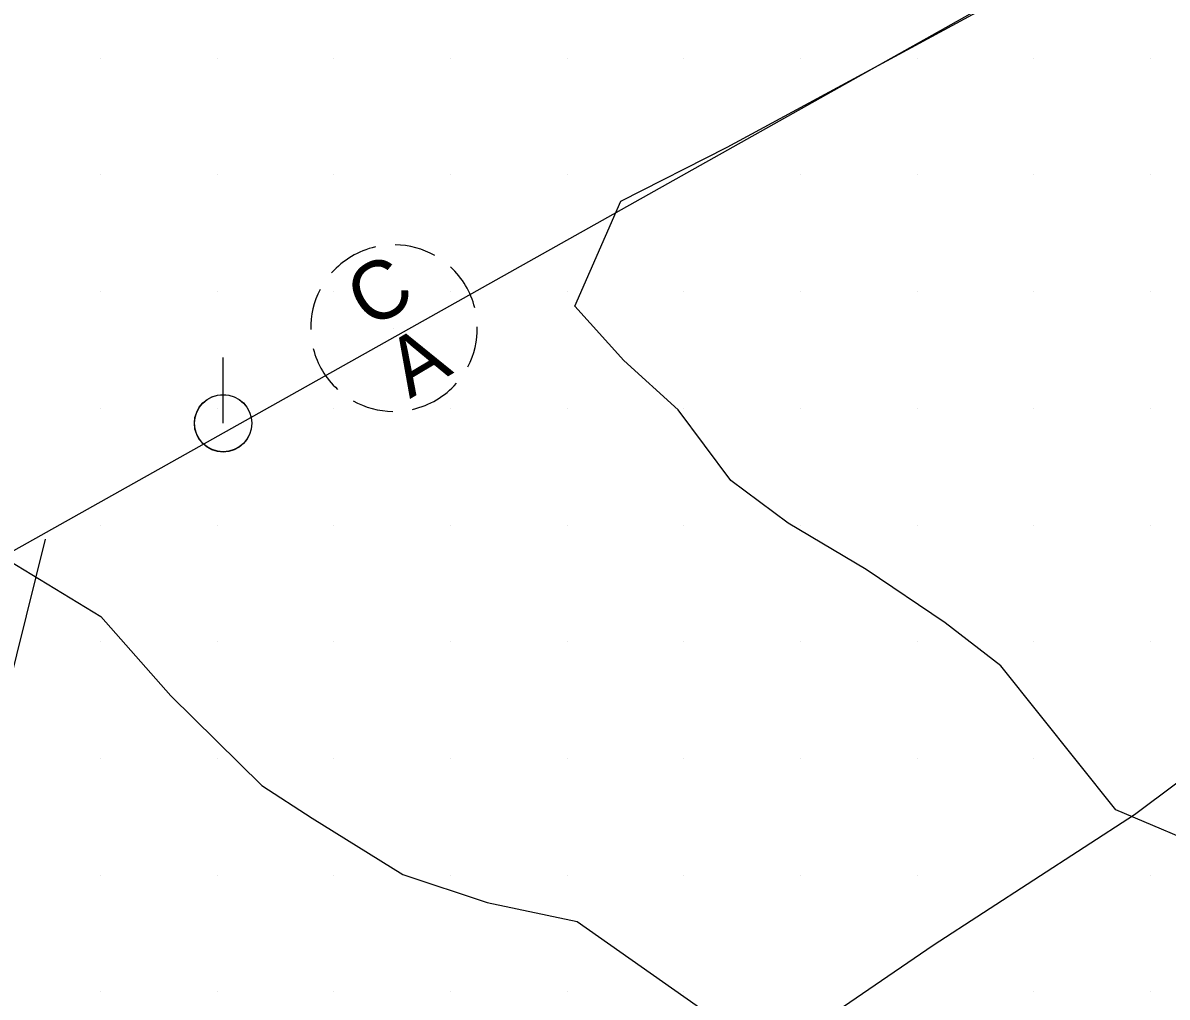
# Model space of a CAD drawing. Extents: x 1548934 to 1561348, y 809680 to 824075.
# Drawn here: x 1551833.4 to 1551931.4, y 810969.6 to 811053 of the extents above; entities that cross this region are included whole.
import ezdxf

# ---------------------------------------------------------------- set-up
doc = ezdxf.new("R2010")
doc.units = 0
for name, color, linetype in [('Exist DTM QL2 LIDAR Elevation Point', 7, 'Continuous'), ('Exist Other Culture Fence Line Leader', 7, 'Continuous'), ('Exist Right of Way Control of Access CA Symbol CELL', 7, 'Continuous'), ('Exist Utilities Other Pole CELL', 7, 'Continuous'), ('Exist Utilities Power Pole CELL', 7, 'Continuous'), ('Exist Vegetation Woods Line', 7, 'Continuous'), ('P_RDY_Dimension_Text', 7, 'Continuous'), ('PH Exist DTM Breakline', 7, 'Continuous')]:
    doc.layers.add(name, color=color, linetype=linetype)

msp = doc.modelspace()

# ---------------------------------------------------------------- linework, layer by layer
at = {"layer": 'Exist DTM QL2 LIDAR Elevation Point'}
for p, q in [((1551840.006, 811050.015), (1551840.006, 811050.015)), ((1551850.007, 811050.015), (1551850.007, 811050.015)), ((1551860.008, 811050.015), (1551860.008, 811050.015)), ((1551870.008, 811050.015), (1551870.008, 811050.015)), ((1551880.009, 811050.015), (1551880.009, 811050.015)), ((1551890.01, 811050.015), (1551890.01, 811050.015)), ((1551900.011, 811050.015), (1551900.011, 811050.015)), ((1551910.012, 811050.015), (1551910.012, 811050.015)), ((1551920.012, 811050.015), (1551920.012, 811050.015)), ((1551930.013, 811050.015), (1551930.013, 811050.015)), ((1551840.006, 811040.014), (1551840.006, 811040.014)), ((1551850.007, 811040.014), (1551850.007, 811040.014)), ((1551860.008, 811040.014), (1551860.008, 811040.014)), ((1551870.008, 811040.014), (1551870.008, 811040.014)), ((1551880.009, 811040.014), (1551880.009, 811040.014)), ((1551890.01, 811040.014), (1551890.01, 811040.014)), ((1551900.011, 811040.014), (1551900.011, 811040.014)), ((1551910.012, 811040.014), (1551910.012, 811040.014)), ((1551920.012, 811040.014), (1551920.012, 811040.014)), ((1551930.013, 811040.014), (1551930.013, 811040.014)), ((1551840.006, 811030.013), (1551840.006, 811030.013)), ((1551850.007, 811030.013), (1551850.007, 811030.013)), ((1551860.008, 811030.013), (1551860.008, 811030.013)), ((1551870.008, 811030.013), (1551870.008, 811030.013)), ((1551880.009, 811030.013), (1551880.009, 811030.013)), ((1551890.01, 811030.013), (1551890.01, 811030.013)), ((1551900.011, 811030.013), (1551900.011, 811030.013)), ((1551910.012, 811030.013), (1551910.012, 811030.013)), ((1551920.012, 811030.013), (1551920.012, 811030.013)), ((1551930.013, 811030.013), (1551930.013, 811030.013)), ((1551840.006, 811020.012), (1551840.006, 811020.012)), ((1551850.007, 811020.012), (1551850.007, 811020.012)), ((1551860.008, 811020.012), (1551860.008, 811020.012)), ((1551870.008, 811020.012), (1551870.008, 811020.012)), ((1551880.009, 811020.012), (1551880.009, 811020.012)), ((1551890.01, 811020.012), (1551890.01, 811020.012)), ((1551900.011, 811020.012), (1551900.011, 811020.012)), ((1551910.012, 811020.012), (1551910.012, 811020.012)), ((1551920.012, 811020.012), (1551920.012, 811020.012)), ((1551930.013, 811020.012), (1551930.013, 811020.012)), ((1551840.006, 811010.012), (1551840.006, 811010.012)), ((1551850.007, 811010.012), (1551850.007, 811010.012)), ((1551860.008, 811010.012), (1551860.008, 811010.012)), ((1551870.008, 811010.012), (1551870.008, 811010.012)), ((1551880.009, 811010.012), (1551880.009, 811010.012)), ((1551890.01, 811010.012), (1551890.01, 811010.012)), ((1551900.011, 811010.012), (1551900.011, 811010.012)), ((1551910.012, 811010.012), (1551910.012, 811010.012)), ((1551920.012, 811010.012), (1551920.012, 811010.012)), ((1551930.013, 811010.012), (1551930.013, 811010.012)), ((1551840.006, 811000.011), (1551840.006, 811000.011)), ((1551850.007, 811000.011), (1551850.007, 811000.011)), ((1551860.008, 811000.011), (1551860.008, 811000.011)), ((1551870.008, 811000.011), (1551870.008, 811000.011)), ((1551880.009, 811000.011), (1551880.009, 811000.011)), ((1551890.01, 811000.011), (1551890.01, 811000.011)), ((1551900.011, 811000.011), (1551900.011, 811000.011)), ((1551910.012, 811000.011), (1551910.012, 811000.011)), ((1551920.012, 811000.011), (1551920.012, 811000.011)), ((1551930.013, 811000.011), (1551930.013, 811000.011)), ((1551840.006, 810990.01), (1551840.006, 810990.01)), ((1551850.007, 810990.01), (1551850.007, 810990.01)), ((1551860.008, 810990.01), (1551860.008, 810990.01)), ((1551870.008, 810990.01), (1551870.008, 810990.01)), ((1551880.009, 810990.01), (1551880.009, 810990.01)), ((1551890.01, 810990.01), (1551890.01, 810990.01)), ((1551900.011, 810990.01), (1551900.011, 810990.01)), ((1551910.012, 810990.01), (1551910.012, 810990.01)), ((1551920.012, 810990.01), (1551920.012, 810990.01)), ((1551840.006, 810980.009), (1551840.006, 810980.009)), ((1551850.007, 810980.009), (1551850.007, 810980.009)), ((1551860.008, 810980.009), (1551860.008, 810980.009)), ((1551870.008, 810980.009), (1551870.008, 810980.009)), ((1551880.009, 810980.009), (1551880.009, 810980.009)), ((1551890.01, 810980.009), (1551890.01, 810980.009)), ((1551900.011, 810980.009), (1551900.011, 810980.009)), ((1551910.012, 810980.009), (1551910.012, 810980.009)), ((1551930.013, 810980.009), (1551930.013, 810980.009)), ((1551840.006, 810970.008), (1551840.006, 810970.008)), ((1551850.007, 810970.008), (1551850.007, 810970.008)), ((1551860.008, 810970.008), (1551860.008, 810970.008)), ((1551870.008, 810970.008), (1551870.008, 810970.008)), ((1551880.009, 810970.008), (1551880.009, 810970.008)), ((1551890.01, 810970.008), (1551890.01, 810970.008)), ((1551920.012, 810970.008), (1551920.012, 810970.008)), ((1551930.013, 810970.008), (1551930.013, 810970.008))]:
    msp.add_line(p, q, dxfattribs=at)
at = {"layer": 'Exist Other Culture Fence Line Leader'}
msp.add_line((1551835.264, 811008.796), (1551825.953, 810971.435), dxfattribs=at)
at = {"layer": 'Exist Right of Way Control of Access CA Symbol CELL'}
msp.add_line((1551865.159, 811026.884), (1551865.159, 811026.884), dxfattribs=at)
for start, end in [(102.93801, 138.55023), (60.55675, 89.14456), (14.16473, 47.32351), (152.34368, 180.9315), (332.34368, 0.9315), (194.16473, 227.32351), (282.93801, 318.55023), (240.55675, 269.14456)]:
    msp.add_arc((1551865.159, 811026.884), 7.14, start, end, dxfattribs=at)
at = {"layer": 'Exist Utilities Other Pole CELL'}
msp.add_circle((1551850.515, 811018.734), 2.463, dxfattribs=at)
at = {"layer": 'Exist Utilities Power Pole CELL'}
for q in [(1551850.515, 811024.359), (1551850.515, 811018.734)]:
    msp.add_line((1551850.515, 811018.734), q, dxfattribs=at)
msp.add_circle((1551850.515, 811018.734), 2.45, dxfattribs=at)
at = {"layer": 'Exist Vegetation Woods Line'}
for points in [[(1551977.926, 810998.298), (1551970.882, 810994.36), (1551960.151, 810989.159), (1551950.009, 810984.466), (1551942.264, 810982.576), (1551935.787, 810981.884), (1551927.037, 810985.601), (1551917.167, 810997.938), (1551912.389, 811001.642), (1551905.641, 811006.197), (1551898.943, 811010.16), (1551894.029, 811013.817), (1551889.505, 811019.897), (1551884.86, 811024.105), (1551880.667, 811028.773), (1551884.611, 811037.753), (1551893.703, 811042.392), (1551949.834, 811072.754)], [(1551832.136, 811006.965), (1551840.027, 811002.19), (1551846.018, 810995.392), (1551853.841, 810987.695), (1551858.155, 810984.9), (1551865.91, 810980.079), (1551873.143, 810977.673), (1551880.871, 810976.047), (1551898.365, 810963.728), (1551908.799, 810955.094), (1551915.868, 810944.698), (1551911.44, 810933.568), (1551901.684, 810926.412), (1551891.003, 810920.618), (1551883.093, 810916.536), (1551874.328, 810910.941), (1551867.511, 810907.233), (1551854.845, 810892.977), (1551851.278, 810888.246), (1551842.251, 810881.187), (1551829.67, 810873.369)]]:
    msp.add_lwpolyline(points, dxfattribs=at)
at = {"layer": 'P_RDY_Dimension_Text'}
msp.add_lwpolyline([(1551792.625, 810879.891), (1551798.87, 810886.607), (1551791.807, 810954.684), (1551790.155, 810983.567), (1551796.354, 810987.521), (1551966.163, 811082.815)], dxfattribs=at)
at = {"layer": 'PH Exist DTM Breakline'}
msp.add_lwpolyline([(1551964.87, 811011.806), (1551950.046, 811001.191), (1551928.639, 810985.193), (1551911.37, 810973.982), (1551899.789, 810966.083), (1551880.246, 810951.204), (1551869.508, 810942.952), (1551844.009, 810925.311), (1551827.482, 810911.465), (1551810.295, 810896.27), (1551800.429, 810887.112), (1551798.705, 810886.522), (1551796.47, 810886.72), (1551794.868, 810885.708)], dxfattribs=at)

# ---------------------------------------------------------------- texts
at = {"layer": 'Exist Right of Way Control of Access CA Symbol CELL'}
for s, p in [('C', (1551863.074, 811026.726)), ('A', (1551866.517, 811020.802))]:
    msp.add_text(s, height=5, rotation=30.74412, dxfattribs=at).set_placement(p)

doc.saveas('drawing.dxf')
